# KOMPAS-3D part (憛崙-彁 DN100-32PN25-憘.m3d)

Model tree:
1. Объединить компоненты:1  (labels: СЕНС-ПР DN100/32PN25)
2. Эскиз:1
3. Операция выдавливания:1
     Расстояние 1 = 14
4. Эскиз:2
5. Операция выдавливания:2
     Расстояние 1 = 14
6. Фаска:1
     Угол = 45; Длина 1 = 2; Длина 2 = 2
7. Фаска:2
     Угол = 45; Длина 1 = 2; Длина 2 = 2

Referenced files in C:\Users\b_ang\Desktop\СЕНС-ПР DN100_32PN25\: СЕНС-ПР DN100_32PN25.a3d
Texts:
  СЕНС-ПР DN100/32PN25-СВ
  Body Specification ( left align )
  Body Specificaton ( centered )
  Трубка  разделительная
  СЕНС-ПР DN100/32PN25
